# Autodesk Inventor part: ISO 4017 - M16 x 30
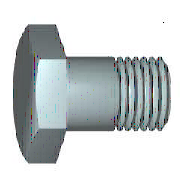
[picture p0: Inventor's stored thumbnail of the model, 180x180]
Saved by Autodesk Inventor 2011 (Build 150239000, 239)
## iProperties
IsCustomPart: 0
Created: 2009-02
Part Number: ISO 4017 - M16 x 30
Material: Stainless Steel, 440C
Description: Hexagon head screws
Document SubType Name: Modeling
Standard: ISO 4017
Designer: V.de Jong
Standard Revision: Third edition 1999-08-15
Standards Organization: ISO
Language: en-US
Size Designation: M16 x 30
Categories: <MemberInstance><Categories><Category DisplayName="Fasteners" InternalName="e4da775c-781d-43d5-af7c-5136215cf5a6" Mnemonic="FSTN"><Category DisplayName="Bolts"
Density: 7.75 g/cm^3
Mass: 84.3823 g
Surface Area: 32.6556 cm^2
Volume: 10.888 cm^3
Author: V.de Jong
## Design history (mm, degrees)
body "Solid1"
workplane "Work Plane1"
revolve "Body" stored, may be unused: angle "d12" = 90 deg
sketch "Sketch2"
  geometry: L1 (0, 13.856)-(12, 6.928); L2 (12, 6.928)-(12, -6.928); L3 (12, -6.928)-(0, -13.856); L4 (0, -13.856)-(-12, -6.928); L5 (-12, -6.928)-(-12, 6.928); L6 (-12, 6.928)-(0, 13.856); 2 further points
  constraints: 12 end point, 1 coincident, 1 vertical, 11 other
  dimensions: "d11" = 24 distance between parallel lines of L5 L2 (= SW)
extrude "Head" join sketch "Sketch2" distance "d3" = 9.2 (= KOH - SD); taper "d4" = 0 deg
revolve "Chamfer1" stored, may be unused: angle "d21" = 90 deg
feature "Thread" dims "d15" = 24 (= GEL), "d16" = 0
chamfer "Chamfer2" distance "d6" = 1.2269 (= -0.5 x SPD + 0.5 x GD); stored, may be unused: second distance "d7" = 1.227 (computed from GUL), angle "d55" = 45 deg
sketch "Sketch1"
  geometry: L1 (0, 11.245)-(0, 8); L2 (6, 8)-(30, 8); L3 (30, 8)-(30, 0); L4 (30, 0)-(-0.8, 0); L5 (-6.96, 0)-(36.16, 0) reference; L6 (-0.8, 0)-(-0.8, 11.245); L7 (-0.8, 11.245)-(0, 11.245); L8 (6, 8)-(4.773, 8); L9 (4.773, 8)-(0, 8); L10 (0, -2.249)-(0, 13.494) reference
  constraints: 16 end point, 2 collinear, 2 perpendicular, 1 parallel
  dimensions: "d0" = 30 distance between parallel lines of L3 L1 (= NLG); "d1" = 24 distance from line of L2.start L3 (= GEL); "d2" = 16 diameter of L2 L4 (= GD); "d9" = 0.8001 distance between parallel lines of L6 L1 (computed from SD); "d10" = 22.49 diameter of L7 L4 (= SD2); "d13" = 1.227 distance of L2.start L8.end (computed from GAL); "d14" = 16 diameter of L9 L4 (= BDM)
sketch "Sketch4"
  geometry: L1 (-10, 12)-(-10, 13.856); L2 (-10, 13.856)-(-8.928, 13.856); L3 (-8.928, 13.856)-(-10, 12); L4 (-11.84, 0)-(1.04, 0) reference; L5 (-0.8, 13.856)-(-10, 13.856) reference; L6 (-10, 6.928)-(-10, 13.856) reference
  constraints: 6 end point, 2 collinear, 1 perpendicular, 1 vertical
  dimensions: "d5" = 30 deg angle of L3 L1 (= ANG1); "d19" = 24 diameter of L1.start L4 (= SW0)
other parameters: "NLG" = 30 [user parameter; used in 1 equation term], "GD" = 16 (= NND) [user parameter; used in 2 equation terms], "BDM" = 16 (= NND) [user parameter; used in 1 equation term], "KOH" = 10 [user parameter; used in 1 equation term], "GEL" = 24 [user parameter; used in 2 equation terms], "SW" = 24 [user parameter; used in 2 equation terms], "SW0" = 24 (= SW) [user parameter; used in 1 equation term], "SPD" = 13.5462 (= NND - 1.2269 x PTC) [user parameter; used in 1 equation term], "SD2" = 22.49 [user parameter; used in 2 equation terms], "SD" = 0.8 [user parameter; used in 2 equation terms], "ANG1" = 30 deg [user parameter; used in 1 equation term], "GAL" = 1.2269 (= 0.61345 x PTC) [user parameter; used in 1 equation term], "GUL" = 1.2269 (= 0.61345 x PTC) [user parameter; used in 1 equation term], "d8" = 0, "RR" = 0.6 [user parameter], "d57" = 0, "d58" = 0, "TPU" = 5 (computed from PTC) [user parameter], "GD1" = 13.5462 (= THREADDIA - 1.2269 x PTC) [user parameter], "THREADDIA" = 16 [user parameter; used in 1 equation term], "SDH" = 22.49 (= SD2) [user parameter], "SDHG" = 6 [user parameter], "TOA" = 30 deg [user parameter], "PTC" = 2 [user parameter; used in 5 equation terms], "NND" = 16 [user parameter; used in 3 equation terms], "E0" = 27.72 [user parameter]
